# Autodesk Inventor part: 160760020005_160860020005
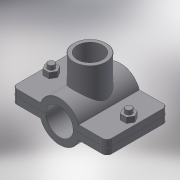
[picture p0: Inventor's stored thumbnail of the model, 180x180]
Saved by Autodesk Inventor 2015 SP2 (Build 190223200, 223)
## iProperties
Created: 2017-05
Part Number: 160760020005_160860020005
Material: Generic
Description: PLASSON SADDLE 20-1/2"
Document SubType Name: Modeling
Designer: KIM
Density: 1 g/cm^3
Appearance: Default
Author: KIM
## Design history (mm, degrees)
derived "16076.ipt"
feature "Solid1::16076.ipt"
feature "Solid2::16076.ipt"
tag "TaggingFeature1"
body "Solid1"
other parameters: "d4" = 45, "d5" = 0, "d6" = 3.5, "d8" = 0.1, "d10" = 0, "d11" = 0.2, "d14" = 24.2203, "d20" = 0.2, "d23" = 0.2, "d36" = 8, "d37" = 6.4, "d38" = 18, "d39" = 0, "d40" = 3, "d41" = 4, "d42" = 0, "d43" = 5, "d44" = 3, "d45" = 0, "d46" = 0.2, "d51" = 33, "d52" = 18.631, "d53" = 18, "d54" = 0, "d57" = 0, "d58" = 21.6, "d60" = 0, "d62" = 8, "d63" = 22.5, "d66" = 0, "G_" = 18.631, "A_" = 33, "L_1" = 45, "l_2" = 18
